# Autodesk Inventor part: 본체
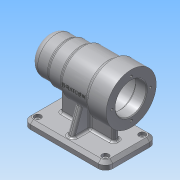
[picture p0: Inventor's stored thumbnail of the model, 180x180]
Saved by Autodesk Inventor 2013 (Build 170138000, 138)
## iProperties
Created: 2016-06
Part Number: 본체
Material: 알루미늄 6061
Document SubType Name: Modeling
Designer: Administrator
Density: 2.71 g/cm^3
Mass: 671.739 g
Surface Area: 646.329 cm^2
Volume: 247.874 cm^3
Author: Administrator
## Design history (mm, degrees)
sketch "스케치1"
  geometry: L1 (-46, 35)-(46, 35); L2 (56, 25)-(56, -25); L3 (46, -35)-(-46, -35); L4 (-56, -25)-(-56, 25); C1 r 2.5 at (-46, 25); C2 r 2.5 at (46, 25); C3 r 2.5 at (46, -25); C4 r 2.5 at (-46, -25); A1 r 10 centre (-46, 25) between (-46, 35) and (-56, 25); A2 r 10 centre (-46, -25) between (-56, -25) and (-46, -35); A3 r 10 centre (46, -25) between (46, -35) and (56, -25); A4 r 10 centre (46, 25) between (56, 25) and (46, 35); 3 further points
  constraints: 8 centre point, 8 end point, 8 point on circle, 8 tangent, 6 equal radius, 4 coincident, 2 midpoint, 2 parallel, 1 horizontal, 1 horizontal alignment, 1 perpendicular, 1 vertical alignment
  dimensions: "d0" = 112 distance between parallel lines of L2 L4; "d2" = 70 distance between parallel lines of L3 L1; "d3" = 10 radius of A1; "d4" = 5 diameter of C1
extrude "돌출1" new body sketch "스케치1" distance "d5" = 10; taper "d6" = 0 deg
sketch "스케치2"
  geometry: L1 (-56, 70)-(56, 70); L2 (-56, 70)-(-56, 104); L3 (-56, 104)-(-28, 104); L4 (-28, 104)-(-28, 100); L5 (-28, 100)-(11, 100); L6 (11, 100)-(11, 97); L7 (11, 97)-(31, 97); L8 (31, 97)-(31, 95); L9 (31, 95)-(56, 95); L10 (56, 95)-(56, 70); 2 further points
  constraints: 20 end point, 5 horizontal, 5 vertical, 1 vertical alignment
  dimensions: "d8" = 112 distance of L1.start L1.end; "d9" = 84 distance between parallel lines of L10 L4; "d10" = 45 distance between parallel lines of L10 L6; "d11" = 25 distance between parallel lines of L10 L8; "d12" = 68 diameter of L3 L1; "d13" = 60 diameter of L5 L1; "d14" = 54 diameter of L7 L1; "d15" = 50 diameter of L9 L1; "d16" = 70 vertical distance of point (0, 0) L1.end
revolve "회전1" sketch "스케치2" stored, may be unused: angle "d17" = 90 deg
sketch "스케치6"
  geometry: A1 r 34 centre (0, 0) between (-34, 0) and (-34, 0) reference; A2 r 26 centre (0, 0) between (-26, 0) and (26, 0); 3 further points
  constraints: 4 point on circle, 2 horizontal alignment, 2 vertical alignment, 1 centre point, 1 coincident
  dimensions: "d44" = 52 diameter of A2
hole "구멍1" sketch "스케치6" at (-26, 0), (26, 0), (0, -26), (0, 26) diameter "d46" = 3.242; stored, may be unused: countersink angle "d50" = 90 deg, drill point angle "d52" = 118 deg; dims "d47" = 8, "d48" = 4, "d49" = 2, "d51" = 11
hole "구멍2" diameter "d55" = 5; stored, may be unused: countersink angle "d59" = 90 deg, drill point angle "d61" = 0 deg; dims "d53" = 10, "d54" = 10, "d56" = 8, "d57" = 9, "d58" = 4, "d60" = 11
hole "구멍3" diameter "d64" = 5; stored, may be unused: countersink angle "d68" = 90 deg, drill point angle "d70" = 0 deg; dims "d62" = 10, "d63" = 10, "d65" = 8, "d66" = 9, "d67" = 4, "d69" = 11
hole "구멍4" diameter "d73" = 5; stored, may be unused: countersink angle "d77" = 90 deg, drill point angle "d79" = 0 deg; dims "d71" = 10, "d72" = 10, "d74" = 8, "d75" = 9, "d76" = 4, "d78" = 11
hole "구멍5" diameter "d82" = 5; stored, may be unused: countersink angle "d86" = 90 deg, drill point angle "d88" = 0 deg; dims "d80" = 10, "d81" = 10, "d83" = 8, "d84" = 9, "d85" = 4, "d87" = 11
node "작업 평면1"
sketch "스케치7"
  geometry: L1 (47.5, 34)-(47.5, -34) reference; 3 further points
  constraints: 1 horizontal alignment, 1 midpoint, 1 other
  dimensions: "d89" = 48 distance from line of L1 point (-0.5, 0)
feature "엠보싱1" sketch "스케치7" dims "d0" = 112, "d2" = 70, "d3" = 10, "d4" = 5, "d90" = 0.5, "d91" = 0
fillet "모깎기1" dims "d92" = 3
fillet "모깎기2" dims "d93" = 10
sketch "스케치8"
  geometry: L1 (-36, 10.173)-(-36, 54); L2 (-36, 54)-(36, 54); L3 (36, 54)-(36, 10); L4 (-56, 0)-(-56, 10) reference; L5 (56, 0)-(56, 10) reference; L6 (-46, 10)-(-56, 10) reference; L7 (56, 10)-(46, 10) reference; 1 further point
  constraints: 6 end point, 2 vertical, 1 horizontal, 1 point on line
  dimensions: "d94" = 20 distance between parallel lines of L4 L1; "d95" = 20 distance between parallel lines of L5 L3; "d96" = 54 distance from line of point (0, 0) L2
extrude "돌출4" join sketch "스케치8" stored distance "d98" = 8; taper "d99" = 0 deg
sketch "스케치9"
  geometry: L1 (-35, 0)-(-35, 10) reference; L2 (-25, 10)-(-35, 10) reference; L3 (35, 10)-(25, 10) reference; L4 (35, 0)-(35, 10) reference; L5 (-28, 10)-(-11.985, 54); L6 (-11.985, 54)-(11.985, 54); L7 (11.985, 54)-(28, 10); 1 further point
  constraints: 6 end point, 2 point on line, 1 equal length, 1 horizontal
  dimensions: "d100" = 7 distance from line of L5.start L1; "d101" = 7 distance from line of L7.end L4; "d102" = 110 deg angle of L3 L7; "d103" = 54 distance from line of point (0, 0) L6
extrude "돌출5" join sketch "스케치9" stored distance "d105" = 8; taper "d106" = 0 deg
sketch "스케치10"
  geometry: L1 (-56, 36)-(-56, 104) reference; L2 (56, 85)-(56, 55) reference; L3 (-56, 70)-(56, 70); L4 (-56, 70)-(-56, 91); L5 (-41, 91)-(-41, 94); L6 (-41, 94)-(13, 94); L7 (13, 94)-(13, 91); L8 (13, 91)-(25, 91); L9 (25, 91)-(25, 87.5); L10 (25, 87.5)-(43, 87.5); L11 (43, 87.5)-(43, 86); L12 (43, 86)-(47, 86); L13 (47, 86)-(47, 80.5); L14 (47, 80.5)-(50, 80.5); L15 (50, 80.5)-(50, 70); L16 (-56, 91)-(-41, 91); 1 further point
  constraints: 28 end point, 6 horizontal, 6 vertical, 2 midpoint, 2 point on line
  dimensions: "d107" = 15 distance of L4.end L5.start; "d109" = 54 distance of L5.end L6.end; "d110" = 12 distance of L7.end L8.end; "d111" = 18 distance of L9.end L10.end; "d112" = 4 distance of L11.end L12.end; "d113" = 3 distance of L13.end L14.end; "d114" = 42 diameter of L16 L3; "d115" = 48 diameter of L6 L3; "d116" = 42 diameter of L8 L3; "d117" = 35 diameter of L10 L3; "d118" = 32 diameter of L12 L3; "d119" = 21 diameter of L14 L3
revolve "회전3" sketch "스케치10" stored, may be unused: angle "d120" = 90 deg
chamfer "모따기1" distance "d121" = 1; stored, may be unused: second distance "d122" = 2, angle "d123" = 45 deg
chamfer "모따기2" distance "d124" = 4; stored, may be unused: second distance "d125" = 2, angle "d126" = 45 deg
fillet "모깎기4" dims "d128" = 0.3
fillet "모깎기5" dims "d129" = 3
fillet "모깎기6" dims "d130" = 3
fillet "모깎기7" dims "d131" = 3
fillet "모깎기8" dims "d132" = 3
fillet "모깎기9" dims "d133" = 3
node "솔리드1"
other parameters: "d97" = 8, "d104" = 8
